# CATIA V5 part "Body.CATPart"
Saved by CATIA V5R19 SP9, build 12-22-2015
Part number: Body
Definition: design
Nomenclature: Body
Source: Unknown
Bounding box of the stored display mesh (mm): x -59 to 59, y -37.5 to 34.5, z 0 to 11
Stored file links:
  Z:\charly_robot\Body.CATPart
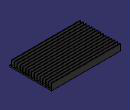
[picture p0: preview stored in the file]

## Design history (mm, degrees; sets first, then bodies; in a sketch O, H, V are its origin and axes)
AxisSystem1: origin (0, 0, 0), X (1, 0, 0), Y (0, 1, 0), Z (0, 0, 1)
Body1 "MANIFOLD_SOLID_BREP #120" (main body)
  Solid1: solid without history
